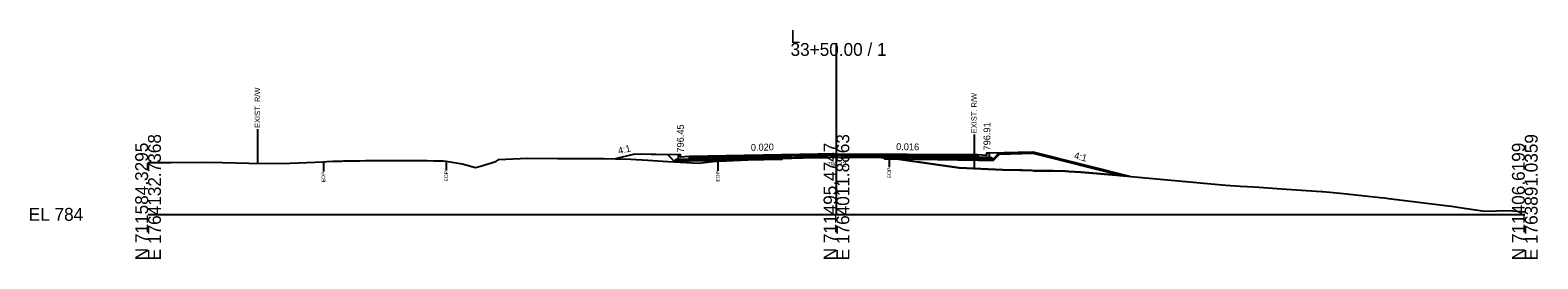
# Model space of a CAD drawing. Extents: x -26 to 5303, y -10 to 9578.
# Drawn here: x 1974.3 to 2302.8, y 3490.3 to 3540.1 of the extents above; entities that cross this region are included whole.
import ezdxf

# ---------------------------------------------------------------- set-up
doc = ezdxf.new("R2010")
doc.units = 0
for name, color, linetype in [('Default', 7, 'Continuous'), ('Exist CMT Pavement', 7, 'Continuous'), ('Exist Cross Section Cell', 7, 'Continuous'), ('Exist XS Ground Line', 7, 'Continuous'), ('Old_Level_10', 7, 'Continuous'), ('Old_Level_3', 7, 'Continuous'), ('Prop CMT Conc Surface', 7, 'Continuous'), ('Prop CMT Concrete Structures', 7, 'Continuous'), ('Prop CMT Pvmt Course 1', 7, 'Continuous'), ('Prop CMT Pvmt Course 1 CG', 7, 'Continuous'), ('Prop CMT Pvmt Course 2', 7, 'Continuous'), ('Prop CMT Pvmt Course 3', 7, 'Continuous'), ('Prop CMT Pvmt Surface', 7, 'Continuous'), ('Prop CMT Slope Grass', 7, 'Continuous'), ('Prop CMT Subgrade Earthwork', 7, 'Continuous'), ('Prop XS Earthwork Shape', 7, 'Continuous'), ('Prop XS Hydro Elevations', 7, 'Continuous'), ('Prop XS SE Text', 7, 'Continuous'), ('Prop XS Side Slope Text', 7, 'Continuous'), ('Prop XS Wedging', 7, 'Continuous')]:
    doc.layers.add(name, color=color, linetype=linetype)

msp = doc.modelspace()

# ---------------------------------------------------------------- linework, layer by layer
at = {"layer": 'Exist CMT Pavement'}
msp.add_lwpolyline([(2138.21, 3512.24), (2138.38, 3512.25), (2139.17, 3512.26), (2140.25, 3512.27), (2140.96, 3512.28), (2141.48, 3512.28), (2142.75, 3512.31), (2144.58, 3512.36), (2146.32, 3512.38), (2147.69, 3512.41), (2148.11, 3512.41), (2148.69, 3512.42), (2150, 3512.42), (2150.79, 3512.41), (2151.69, 3512.41), (2152.91, 3512.41), (2153.48, 3512.42), (2153.89, 3512.42), (2155.27, 3512.42), (2157.13, 3512.44), (2158.84, 3512.44), (2159.93, 3512.39), (2160.45, 3512.36)], dxfattribs=at)
at = {"layer": 'Exist Cross Section Cell'}
for p, q in [((2150, 3500), (2150, 3537.32)), ((2000, 3500), (2150, 3500)), ((2150, 3500), (2300, 3500))]:
    msp.add_line(p, q, dxfattribs=at)
at = {"layer": 'Exist XS Ground Line'}
msp.add_lwpolyline([(2000, 3511.32), (2004.93, 3511.28), (2011.44, 3511.4), (2016.23, 3511.27), (2021.99, 3511.14), (2029.1, 3511.1), (2038.2, 3511.41), (2038.93, 3511.5), (2040.27, 3511.56), (2040.82, 3511.57), (2042.18, 3511.61), (2042.61, 3511.62), (2043.18, 3511.64), (2044.4, 3511.66), (2045.29, 3511.67), (2046.18, 3511.69), (2047.4, 3511.71), (2047.97, 3511.72), (2048.39, 3511.73), (2049.76, 3511.76), (2051.62, 3511.76), (2053.34, 3511.76), (2054.6, 3511.74), (2055.12, 3511.73), (2055.84, 3511.74), (2056.91, 3511.74), (2057.7, 3511.73), (2060.06, 3511.71), (2060.8, 3511.7), (2062.28, 3511.68), (2062.87, 3511.67), (2063.2, 3511.66), (2064.27, 3511.64), (2064.94, 3511.6), (2068.42, 3511.01), (2071.36, 3510.19), (2072.44, 3510.46), (2074.11, 3511.02), (2075.77, 3511.52), (2076.45, 3511.94), (2082.58, 3512.25), (2089.26, 3512.15), (2092.79, 3512.19), (2099.24, 3512.18), (2105.18, 3512.01), (2108.91, 3511.77), (2113.25, 3511.54), (2120.04, 3511.13), (2123.74, 3511.57), (2124.14, 3511.56), (2125.04, 3511.62), (2125.48, 3511.63), (2125.97, 3511.66), (2126.65, 3511.7), (2127.59, 3511.74), (2128.44, 3511.78), (2129.07, 3511.81), (2130.23, 3511.88), (2132.17, 3511.98), (2133.81, 3512.06), (2135.27, 3512.12), (2135.59, 3512.13), (2136.03, 3512.15), (2138.38, 3512.25), (2139.17, 3512.26), (2140.25, 3512.27), (2140.96, 3512.28), (2141.48, 3512.28), (2142.75, 3512.31), (2144.58, 3512.36), (2146.32, 3512.38), (2147.69, 3512.41), (2148.11, 3512.41), (2148.69, 3512.42), (2150, 3512.42), (2150.79, 3512.41), (2151.69, 3512.41), (2152.91, 3512.41), (2153.48, 3512.42), (2153.89, 3512.42), (2155.27, 3512.42), (2157.13, 3512.44), (2158.84, 3512.44), (2159.82, 3512.38), (2160.45, 3512.36), (2160.84, 3512.34), (2161.5, 3512.32), (2164.55, 3511.89), (2176.72, 3510.11), (2186.26, 3509.66), (2190.02, 3509.61), (2190.47, 3509.6), (2192.56, 3509.55), (2193.1, 3509.51), (2194.06, 3509.51), (2195.28, 3509.51), (2196.09, 3509.48), (2197.22, 3509.44), (2199.89, 3509.38), (2200.66, 3509.36), (2203.24, 3509.17), (2211.01, 3508.5), (2234.88, 3506.39), (2237.99, 3506.17), (2241.02, 3505.98), (2248.09, 3505.49), (2255.69, 3505), (2256.02, 3505), (2260.48, 3504.57), (2268.49, 3503.67), (2269.39, 3503.57), (2270.29, 3503.46), (2276.87, 3502.68), (2282.7, 3501.94), (2284.03, 3501.76), (2285.83, 3501.46), (2291.18, 3500.69), (2296.47, 3500.8), (2298.33, 3500.69), (2300, 3500.57)], dxfattribs=at)
at = {"layer": 'Old_Level_10'}
for p, q in [((2023.83, 3518.53), (2023.83, 3511.13)), ((2179.99, 3517.36), (2179.99, 3509.96)), ((2161.5, 3512.32), (2161.5, 3510.27)), ((2038.2, 3511.41), (2038.2, 3509.36)), ((2064.94, 3511.6), (2064.94, 3509.55)), ((2124.14, 3511.56), (2124.14, 3509.51))]:
    msp.add_line(p, q, dxfattribs=at)
at = {"layer": 'Prop CMT Conc Surface'}
for points in [[(2116, 3512.45), (2116, 3512.95), (2115.5, 3512.95)], [(2118, 3512.57), (2116, 3512.45)], [(2180.8, 3513.02), (2182.8, 3512.91)], [(2182.8, 3512.91), (2182.8, 3513.41), (2183.3, 3513.41)]]:
    msp.add_lwpolyline(points, dxfattribs=at)
at = {"layer": 'Prop CMT Concrete Structures'}
for points in [[(2118, 3512.57), (2116, 3512.45), (2116, 3512.95), (2115.5, 3512.95)], [(2115.5, 3512.95), (2115.5, 3511.93), (2118, 3511.98)], [(2118, 3511.98), (2118, 3512.57)], [(2180.8, 3513.02), (2182.8, 3512.91), (2182.8, 3513.41), (2183.3, 3513.41)], [(2183.3, 3513.41), (2183.3, 3512.4), (2180.8, 3512.44)], [(2180.8, 3512.44), (2180.8, 3513.02)]]:
    msp.add_lwpolyline(points, dxfattribs=at)
at = {"layer": 'Prop CMT Pvmt Course 1'}
for p, q in [((2150, 3513.21), (2180.8, 3513.02)), ((2180.8, 3512.77), (2160.45, 3512.79))]:
    msp.add_line(p, q, dxfattribs=at)
for points in [[(2150, 3513.21), (2118, 3512.57)], [(2118, 3512.32), (2138.21, 3512.72)], [(2118, 3512.57), (2118, 3512.32)], [(2138.21, 3512.72), (2150, 3512.96)], [(2138.21, 3512.72), (2138.21, 3512.72)], [(2150, 3512.96), (2150, 3513.21)], [(2150, 3512.96), (2150, 3512.96), (2150, 3512.96)], [(2160.45, 3512.79), (2150, 3512.96)], [(2160.45, 3512.79), (2160.45, 3512.79)], [(2180.8, 3513.02), (2180.8, 3512.77)]]:
    msp.add_lwpolyline(points, dxfattribs=at)
at = {"layer": 'Prop CMT Pvmt Course 1 CG'}
for points in [[(2180.8, 3512.44), (2183.8, 3512.39), (2184.14, 3512.05)], [(2180.8, 3512.11), (2180.8, 3512.44)], [(2184.14, 3512.05), (2180.8, 3512.11)], [(2118, 3511.98), (2115, 3511.92), (2114.66, 3511.58)], [(2114.66, 3511.58), (2118, 3511.65)], [(2118, 3511.65), (2118, 3511.98)]]:
    msp.add_lwpolyline(points, dxfattribs=at)
at = {"layer": 'Prop CMT Pvmt Course 2'}
for p, q in [((2160.45, 3512.79), (2180.8, 3512.77)), ((2180.8, 3512.44), (2160.45, 3512.46))]:
    msp.add_line(p, q, dxfattribs=at)
for points in [[(2138.21, 3512.72), (2118, 3512.32)], [(2118, 3511.98), (2138.21, 3512.39)], [(2118, 3512.32), (2118, 3511.98)], [(2138.21, 3512.39), (2138.21, 3512.72)], [(2160.45, 3512.46), (2160.45, 3512.79)], [(2180.8, 3512.77), (2180.8, 3512.44)]]:
    msp.add_lwpolyline(points, dxfattribs=at)
at = {"layer": 'Prop CMT Pvmt Course 3'}
for p, q in [((2160.45, 3512.46), (2180.8, 3512.44)), ((2180.8, 3512.11), (2160.45, 3512.12))]:
    msp.add_line(p, q, dxfattribs=at)
for points in [[(2138.21, 3512.39), (2118, 3511.98)], [(2118, 3511.65), (2138.21, 3512.05)], [(2138.21, 3512.05), (2138.21, 3512.39)], [(2160.45, 3512.12), (2160.45, 3512.46)], [(2180.8, 3512.44), (2180.8, 3512.11)], [(2118, 3511.98), (2118, 3511.65)]]:
    msp.add_lwpolyline(points, dxfattribs=at)
at = {"layer": 'Prop CMT Pvmt Surface'}
msp.add_line((2150, 3513.21), (2180.8, 3513.02), dxfattribs=at)
msp.add_lwpolyline([(2150, 3513.21), (2118, 3512.57)], dxfattribs=at)
at = {"layer": 'Prop CMT Slope Grass'}
for points in [[(2115.5, 3512.95), (2106, 3513.14), (2101.87, 3512.11)], [(2183.3, 3513.41), (2192.8, 3513.6), (2214.42, 3508.2)]]:
    msp.add_lwpolyline(points, dxfattribs=at)
at = {"layer": 'Prop CMT Subgrade Earthwork'}
for p, q in [((2138.21, 3512.05), (2138.21, 3512.24)), ((2160.45, 3512.12), (2160.45, 3512.36)), ((2160.45, 3512.12), (2180.8, 3512.11))]:
    msp.add_line(p, q, dxfattribs=at)
for points in [[(2118, 3511.65), (2114.66, 3511.58), (2113.25, 3512.99)], [(2138.21, 3512.05), (2118, 3511.65)], [(2180.8, 3512.11), (2184.14, 3512.05), (2185.54, 3513.46)]]:
    msp.add_lwpolyline(points, dxfattribs=at)
at = {"layer": 'Prop XS Earthwork Shape'}
for points in [[(2106, 3513.14), (2101.87, 3512.11), (2105.18, 3512.01), (2108.91, 3511.77), (2113.25, 3511.54), (2120.04, 3511.13), (2123.74, 3511.57), (2124.14, 3511.56), (2125.04, 3511.62), (2125.48, 3511.63), (2125.97, 3511.66), (2126.65, 3511.7), (2127.59, 3511.74), (2128.44, 3511.78), (2129.07, 3511.81), (2130.23, 3511.88), (2130.69, 3511.9), (2118, 3511.65), (2114.66, 3511.58), (2113.25, 3512.99)], [(2130.23, 3511.88), (2130.69, 3511.9), (2118, 3511.65), (2114.66, 3511.58), (2113.25, 3512.99), (2106, 3513.14), (2101.87, 3512.11), (2105.18, 3512.01), (2108.91, 3511.77), (2113.25, 3511.54), (2120.04, 3511.13), (2123.74, 3511.57), (2124.14, 3511.56), (2125.04, 3511.62), (2125.48, 3511.63), (2125.97, 3511.66), (2126.65, 3511.7), (2127.59, 3511.74), (2128.44, 3511.78), (2129.07, 3511.81)], [(2130.69, 3511.9), (2132.17, 3511.98), (2133.81, 3512.06), (2135.27, 3512.12), (2135.59, 3512.13), (2136.03, 3512.15), (2137.38, 3512.21), (2138.21, 3512.24), (2138.21, 3512.05)], [(2135.59, 3512.13), (2136.03, 3512.15), (2137.38, 3512.21), (2138.21, 3512.24), (2138.21, 3512.05), (2130.69, 3511.9), (2132.17, 3511.98), (2133.81, 3512.06), (2135.27, 3512.12)], [(2160.45, 3512.12), (2163.23, 3512.08), (2161.5, 3512.32), (2160.45, 3512.36)], [(2160.45, 3512.36), (2161.5, 3512.32), (2163.23, 3512.08), (2160.45, 3512.12)], [(2194.06, 3509.51), (2195.28, 3509.51), (2196.09, 3509.48), (2197.22, 3509.44), (2199.89, 3509.38), (2200.66, 3509.36), (2203.24, 3509.17), (2211.01, 3508.5), (2212.49, 3508.37), (2192.8, 3513.29), (2185.54, 3513.14), (2184.14, 3511.74), (2180.8, 3511.79), (2163.23, 3512.08), (2164.55, 3511.89), (2176.72, 3510.11), (2186.26, 3509.66), (2190.02, 3509.61), (2190.47, 3509.6), (2192.56, 3509.55), (2193.1, 3509.51)], [(2184.14, 3511.74), (2185.54, 3513.14), (2192.8, 3513.29), (2212.49, 3508.37), (2211.01, 3508.5), (2203.24, 3509.17), (2200.66, 3509.36), (2199.89, 3509.38), (2197.22, 3509.44), (2196.09, 3509.48), (2195.28, 3509.51), (2194.06, 3509.51), (2193.1, 3509.51), (2192.56, 3509.55), (2190.47, 3509.6), (2190.02, 3509.61), (2186.26, 3509.66), (2176.72, 3510.11), (2164.55, 3511.89), (2163.23, 3512.08), (2180.8, 3511.79)]]:
    msp.add_lwpolyline(points, close=True, dxfattribs=at)
at = {"layer": 'Prop XS Wedging'}
msp.add_lwpolyline([(2138.38, 3512.25), (2138.38, 3512.72), (2139.17, 3512.74), (2140.25, 3512.76), (2140.96, 3512.78), (2141.48, 3512.79), (2142.75, 3512.81), (2144.58, 3512.85), (2146.32, 3512.88), (2147.69, 3512.91), (2148.11, 3512.92), (2148.69, 3512.93), (2150, 3512.96), (2150.79, 3512.94), (2151.69, 3512.92), (2152.91, 3512.9), (2153.48, 3512.89), (2153.89, 3512.88), (2155.26, 3512.85), (2157.13, 3512.81), (2158.84, 3512.78), (2159.93, 3512.76), (2160.45, 3512.75), (2160.45, 3512.36), (2159.93, 3512.39), (2158.84, 3512.44), (2157.13, 3512.44), (2155.26, 3512.42), (2153.89, 3512.42), (2153.48, 3512.42), (2152.91, 3512.41), (2151.69, 3512.41), (2150.79, 3512.41), (2150, 3512.42), (2148.69, 3512.42), (2148.11, 3512.41), (2147.69, 3512.41), (2146.32, 3512.38), (2144.58, 3512.36), (2142.75, 3512.31), (2141.48, 3512.28), (2140.96, 3512.28), (2140.25, 3512.27), (2139.17, 3512.26)], close=True, dxfattribs=at)

# ---------------------------------------------------------------- texts
at = {"layer": 'Default'}
msp.add_text('-', height=0.0001, dxfattribs=at).set_placement((2000, 3500))
at = {"layer": 'Exist Cross Section Cell'}
for s, p in [('L', (2140, 3537.32)), ('33+50.00 / 1', (2140, 3534.52)), ('EL 784', (1974, 3498.6))]:
    msp.add_text(s, height=2.8, dxfattribs=at).set_placement(p)
for s, p in [('N 711584.3295', (2000, 3490)), ('E 1764132.7368', (2002.8, 3490)), ('N 711495.4747', (2150, 3490)), ('E 1764011.8863', (2152.8, 3490)), ('N 711406.6199', (2300, 3490)), ('E 1763891.0359', (2302.8, 3490))]:
    msp.add_text(s, height=2.8, rotation=90, dxfattribs=at).set_placement(p)
at = {"layer": 'Old_Level_10'}
for s, height, p in [('EXIST. R/W', 1.181, (2024.42, 3518.83)), ('EXIST. R/W', 1.181, (2180.58, 3517.66)), ('EOP', 0.787, (2038.6, 3506.97)), ('EOP', 0.787, (2065.34, 3507.15)), ('EOP', 0.787, (2124.54, 3507.11)), ('EOP', 0.787, (2161.89, 3507.87))]:
    msp.add_text(s, height=height, rotation=90, dxfattribs=at).set_placement(p)
at = {"layer": 'Old_Level_3'}
msp.add_text('796.42', height=1, dxfattribs=at).set_placement((2147.96, 3510.42))
at = {"layer": 'Prop XS Hydro Elevations'}
for s, p in [('796.45', (2116.75, 3513.45)), ('796.91', (2183.55, 3513.91))]:
    msp.add_text(s, height=1.5, rotation=90, dxfattribs=at).set_placement(p)
at = {"layer": 'Prop XS SE Text'}
for s, rotation, p in [('0.020', 1.1458, (2131.36, 3513.83)), ('0.016', 359.0753, (2162.99, 3514))]:
    msp.add_text(s, height=1.5, rotation=rotation, dxfattribs=at).set_placement(p)
at = {"layer": 'Prop XS Side Slope Text'}
for rotation, p in [(14.0362, (2102.6, 3513.06)), (345.9638, (2201.67, 3512.15))]:
    msp.add_text('4:1', height=1.5, rotation=rotation, dxfattribs=at).set_placement(p)

doc.saveas('drawing.dxf')
